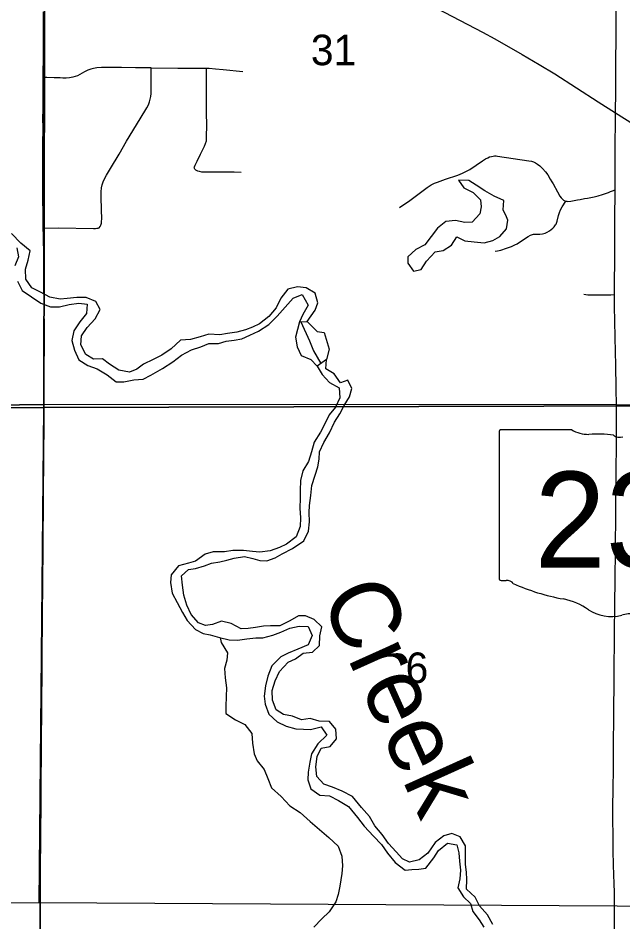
# Model space of a CAD drawing. Extents: x 0 to 34, y 0 to 22.
# Drawn here: x 3.685 to 4.1, y 14.389 to 15.009 of the extents above; entities that cross this region are included whole.
import ezdxf

# ---------------------------------------------------------------- set-up
doc = ezdxf.new("R2010")
doc.units = 0
for name, color, linetype in [('GM_X_Corporation', 7, 'Continuous'), ('GM_X_County_Road', 7, 'Continuous'), ('GM_X_Major_River', 7, 'Continuous'), ('GM_X_Major_River_Text', 7, 'Continuous'), ('GM_X_Minor_Lake', 7, 'Continuous'), ('GM_X_Minor_River', 7, 'Continuous'), ('GM_X_Section_Text', 7, 'Continuous'), ('GM_X_State_Location', 7, 'Continuous'), ('GM_X_State_Route', 7, 'Continuous'), ('GM_X_State_Shield', 7, 'Continuous'), ('GM_X_Township_Road', 7, 'Continuous'), ('GM_X_US_Route', 7, 'Continuous')]:
    doc.layers.add(name, color=color, linetype=linetype)

msp = doc.modelspace()

# ---------------------------------------------------------------- linework, layer by layer
at = {"layer": 'GM_X_Corporation'}
for points in [[(3.70377, 15.25213), (4.22309, 15.24934), (4.21755, 14.74349), (3.70275, 14.74227), (3.70371, 15.24512)], [(3.19551, 15.23797), (3.70371, 15.24512), (3.70275, 14.74227), (3.19987, 14.73736)], [(4.21755, 14.74349), (4.22002, 14.74366), (4.21532, 14.39943), (3.69961, 14.40239), (3.70275, 14.74227)], [(3.19987, 14.73736), (3.70275, 14.74227), (3.69961, 14.40239), (3.19505, 14.4011), (3.19438, 14.73721)]]:
    msp.add_lwpolyline(points, close=True, dxfattribs=at)
for points in [[(3.23219, 14.73782), (3.70287, 14.74434), (3.70292, 14.75501), (3.70303, 14.76775), (3.70304, 14.77242), (3.70314, 14.78236), (3.70311, 14.79541), (3.70302, 14.81125), (3.70283, 14.82865), (3.70272, 14.84636), (3.70258, 14.86004), (3.70248, 14.86546), (3.70234, 14.87231), (3.70232, 14.87417), (3.70228, 14.87728), (3.70217, 14.88318), (3.70216, 14.89312), (3.70214, 14.90181), (3.70217, 14.90647), (3.70219, 14.91392), (3.70222, 14.92325), (3.70226, 14.93319), (3.70225, 14.94159), (3.70238, 14.94561), (3.70236, 14.9484), (3.70239, 14.95057), (3.70236, 14.95615), (3.70235, 14.96081), (3.70234, 14.96547), (3.70235, 14.96878), (3.70235, 14.96921), (3.70251, 14.98412), (3.70254, 14.99252), (3.70258, 15.00309), (3.70261, 15.01364)], [(4.46985, 14.74372), (4.0958, 14.74406), (3.70287, 14.74434), (3.70292, 14.75501), (3.70303, 14.76775), (3.70304, 14.77242), (3.70314, 14.78236), (3.70311, 14.79541), (3.70302, 14.81125), (3.70283, 14.82865), (3.70272, 14.84636), (3.70258, 14.86004), (3.70248, 14.86546), (3.70234, 14.87231), (3.70232, 14.87417), (3.70228, 14.87728), (3.70217, 14.88318), (3.70216, 14.89312), (3.70214, 14.90181), (3.70217, 14.90647), (3.70219, 14.91392), (3.70222, 14.92325), (3.70226, 14.93319), (3.70225, 14.94159), (3.70238, 14.94561), (3.70236, 14.9484), (3.70239, 14.95057), (3.70236, 14.95615), (3.70235, 14.96081), (3.70234, 14.96547), (3.70235, 14.96878), (3.70235, 14.96921), (3.70251, 14.98412), (3.70254, 14.99252), (3.70258, 15.00309), (3.70261, 15.01364)], [(3.70019, 14.37188), (3.7003, 14.3899), (3.70042, 14.40576), (3.7004, 14.42254), (3.70061, 14.4502), (3.70081, 14.47103), (3.70082, 14.48439), (3.70098, 14.50614), (3.7011, 14.51919), (3.70113, 14.52883), (3.70121, 14.54095), (3.70143, 14.56051), (3.70145, 14.56113), (3.70146, 14.56205), (3.70145, 14.56236), (3.70145, 14.56298), (3.70144, 14.56328), (3.70145, 14.56421), (3.70148, 14.56856), (3.70155, 14.56979), (3.7015, 14.57383), (3.70148, 14.58004), (3.70164, 14.58936), (3.70167, 14.59495), (3.7019, 14.62604), (3.70208, 14.6422), (3.70213, 14.65277), (3.70234, 14.67546), (3.70237, 14.68478), (3.7025, 14.70498), (3.70283, 14.73543), (3.70287, 14.74434), (3.23219, 14.73782)], [(4.46985, 14.74372), (4.0958, 14.74406), (3.70287, 14.74434), (3.70283, 14.73543), (3.7025, 14.70498), (3.70237, 14.68478), (3.70234, 14.67546), (3.70213, 14.65277), (3.70208, 14.6422), (3.7019, 14.62604), (3.70167, 14.59495), (3.70164, 14.58936), (3.70148, 14.58004), (3.7015, 14.57383), (3.70155, 14.56979), (3.70148, 14.56856), (3.70145, 14.56421), (3.70144, 14.56328), (3.70145, 14.56298), (3.70145, 14.56236), (3.70146, 14.56205), (3.70145, 14.56113), (3.70143, 14.56051), (3.70121, 14.54095), (3.70113, 14.52883), (3.7011, 14.51919), (3.70098, 14.50614), (3.70082, 14.48439), (3.70081, 14.47103), (3.70061, 14.4502), (3.7004, 14.42254), (3.70042, 14.40576), (3.7003, 14.3899), (3.70019, 14.37188)]]:
    msp.add_lwpolyline(points, dxfattribs=at)
at = {"layer": 'GM_X_County_Road'}
for points in [[(3.70259, 14.86518), (3.70245, 14.87203), (3.70244, 14.8739), (3.70239, 14.877), (3.70229, 14.88291), (3.70227, 14.89284), (3.70226, 14.90153), (3.70229, 14.90619), (3.7023, 14.91364), (3.70233, 14.92297), (3.70237, 14.93292), (3.70236, 14.94131), (3.70249, 14.94533), (3.70248, 14.94812), (3.7025, 14.95029), (3.70247, 14.95588), (3.70246, 14.96053), (3.70245, 14.9652), (3.70246, 14.96851), (3.70246, 14.96893), (3.70262, 14.98385), (3.70265, 14.99224), (3.70269, 15.00281), (3.70272, 15.01337)], [(3.70298, 14.74357), (3.70298, 14.74406), (3.70304, 14.75474), (3.70314, 14.76748), (3.70316, 14.77215), (3.70325, 14.78208), (3.70322, 14.79513), (3.70313, 14.81097), (3.70294, 14.82837), (3.70283, 14.84609), (3.70269, 14.85977), (3.70259, 14.86518)], [(3.7003, 14.3716), (3.70041, 14.38963), (3.70053, 14.40548), (3.70052, 14.42227), (3.70072, 14.44993), (3.70092, 14.47075), (3.70093, 14.48412), (3.7011, 14.50587), (3.70121, 14.51892), (3.70124, 14.52856), (3.70133, 14.54068), (3.70154, 14.56024), (3.70156, 14.56085), (3.70157, 14.56177), (3.70156, 14.56208), (3.70156, 14.5627), (3.70156, 14.56393), (3.70159, 14.56828), (3.70166, 14.56952), (3.70162, 14.57356), (3.70159, 14.57977), (3.70175, 14.58908), (3.70178, 14.59468), (3.70201, 14.62576), (3.70219, 14.64192), (3.70225, 14.65249), (3.70245, 14.67518), (3.70248, 14.6845), (3.70262, 14.7047), (3.70294, 14.73516), (3.70298, 14.74357)]]:
    msp.add_lwpolyline(points, dxfattribs=at)
at = {"layer": 'GM_X_Major_River'}
for points in [[(3.74309, 14.77558), (3.73702, 14.77525), (3.73173, 14.77851), (3.72817, 14.78518), (3.72859, 14.79125), (3.73262, 14.7971), (3.73798, 14.80294), (3.74144, 14.80936), (3.73844, 14.81489), (3.73182, 14.81759), (3.72537, 14.81764), (3.71892, 14.81693), (3.71398, 14.8164), (3.70697, 14.81778), (3.70054, 14.82125), (3.6945, 14.82433), (3.69036, 14.83024), (3.69022, 14.83707), (3.69198, 14.84332), (3.69335, 14.84957), (3.68694, 14.85493), (3.68073, 14.86143)], [(3.68426, 14.85173), (3.68535, 14.84546), (3.68303, 14.8394)], [(3.68485, 14.82876), (3.68803, 14.82248), (3.69445, 14.81807), (3.70087, 14.81384), (3.7073, 14.81133), (3.71356, 14.81128), (3.72021, 14.81294), (3.72686, 14.81384), (3.73255, 14.81304), (3.73212, 14.80659), (3.72753, 14.80093), (3.7235, 14.7947), (3.72212, 14.78807), (3.72378, 14.78161), (3.72696, 14.77494), (3.733, 14.7711), (3.73943, 14.76859), (3.74623, 14.76455), (3.75246, 14.75976), (3.75777, 14.75972), (3.76461, 14.76119), (3.77107, 14.76171), (3.77621, 14.76432), (3.78421, 14.76901), (3.79127, 14.77351)], [(3.88349, 14.80126), (3.88905, 14.809), (3.89079, 14.81392), (3.88913, 14.82057), (3.8829, 14.82423), (3.87683, 14.82484), (3.87018, 14.82337), (3.86558, 14.81715), (3.86231, 14.81053), (3.85714, 14.8045), (3.85084, 14.79961), (3.84608, 14.79737), (3.84114, 14.79552), (3.83524, 14.79385), (3.82897, 14.79295), (3.82366, 14.79204), (3.81607, 14.79248), (3.81017, 14.79063), (3.80352, 14.78878), (3.79669, 14.78845), (3.79019, 14.78243), (3.78371, 14.77812), (3.77781, 14.77513), (3.77133, 14.77195), (3.76656, 14.76838), (3.76161, 14.76633), (3.75441, 14.76772), (3.748, 14.77194), (3.74309, 14.77558)], [(3.79127, 14.77351), (3.79737, 14.77801), (3.80423, 14.78176), (3.81069, 14.78379), (3.81602, 14.78603), (3.82266, 14.78598), (3.82799, 14.78765), (3.83349, 14.78836), (3.83881, 14.78927), (3.84415, 14.79189), (3.85024, 14.7945), (3.85729, 14.799), (3.86302, 14.80483), (3.86838, 14.81106), (3.87393, 14.81708), (3.88021, 14.81969), (3.88414, 14.81245), (3.88068, 14.80603), (3.87836, 14.80092), (3.88349, 14.80126)], [(3.88349, 14.80126), (3.89046, 14.79438), (3.8952, 14.79359), (3.89869, 14.78228), (3.89677, 14.77517)], [(3.89677, 14.77517), (3.89047, 14.77048), (3.89385, 14.76476), (3.89893, 14.75941), (3.90554, 14.75556), (3.90587, 14.74892), (3.90298, 14.7423), (3.89858, 14.73721), (3.89569, 14.73098), (3.89261, 14.72531), (3.88838, 14.71832), (3.88663, 14.71169), (3.88449, 14.70507), (3.88065, 14.69865), (3.87908, 14.69202), (3.87865, 14.68519), (3.8788, 14.67988), (3.87856, 14.67305), (3.8789, 14.6666), (3.87866, 14.66053), (3.87595, 14.65353), (3.86928, 14.64846), (3.86452, 14.64622), (3.85824, 14.6438), (3.85102, 14.64291), (3.84609, 14.64333), (3.83984, 14.64413), (3.83243, 14.644), (3.82674, 14.64328), (3.81915, 14.64315), (3.81344, 14.64149), (3.80696, 14.63679), (3.80221, 14.6355), (3.79536, 14.63366), (3.79019, 14.62743), (3.78977, 14.62213), (3.79086, 14.61491), (3.79442, 14.60843), (3.79797, 14.60157), (3.80116, 14.59605), (3.80699, 14.58993), (3.8121, 14.58724), (3.81702, 14.58625), (3.82346, 14.5845), (3.83009, 14.58293), (3.83578, 14.5827), (3.84205, 14.5836), (3.84831, 14.58412), (3.85306, 14.58427), (3.86009, 14.58612), (3.86542, 14.58816), (3.8717, 14.59077), (3.87797, 14.59224), (3.88423, 14.592), (3.88703, 14.58572), (3.88414, 14.57948), (3.87709, 14.5765), (3.87062, 14.57371), (3.86548, 14.57109), (3.85937, 14.56506), (3.85666, 14.55788), (3.8549, 14.55125), (3.85409, 14.54424), (3.85481, 14.53873), (3.85722, 14.53188), (3.86288, 14.52653), (3.86912, 14.52363), (3.87574, 14.52169), (3.88105, 14.52146), (3.8858, 14.52142), (3.89321, 14.52307), (3.89715, 14.51754), (3.89085, 14.51152), (3.88643, 14.50453), (3.88544, 14.49885), (3.88425, 14.49203), (3.88402, 14.48672), (3.88606, 14.48063), (3.89229, 14.47622), (3.89893, 14.47579), (3.90517, 14.47252), (3.91197, 14.46849), (3.91817, 14.46085), (3.92268, 14.45494), (3.92908, 14.44806), (3.93454, 14.44233), (3.93867, 14.4366), (3.94394, 14.43011), (3.95073, 14.42475), (3.95548, 14.42528), (3.96022, 14.42544), (3.96497, 14.42616), (3.97052, 14.43333), (3.97379, 14.43823), (3.97989, 14.44331), (3.98634, 14.44231), (3.98763, 14.4368), (3.98815, 14.43111), (3.98887, 14.42484), (3.98825, 14.41878), (3.98707, 14.41271)], [(3.99221, 14.44151), (3.98846, 14.44761), (3.98279, 14.44993), (3.97747, 14.44845), (3.97136, 14.44375), (3.96637, 14.43658), (3.96046, 14.43189), (3.95381, 14.43023), (3.94889, 14.43254), (3.94475, 14.43732), (3.93929, 14.44305), (3.93497, 14.44934), (3.92989, 14.45526), (3.92634, 14.46155), (3.92088, 14.46785), (3.91467, 14.47529), (3.90768, 14.47895), (3.90087, 14.48185), (3.895, 14.48379), (3.89011, 14.48914), (3.8894, 14.49578), (3.8904, 14.5028), (3.8931, 14.50847), (3.89937, 14.50975), (3.90377, 14.51484), (3.90325, 14.52148), (3.89893, 14.52682), (3.89172, 14.52707), (3.88566, 14.52882), (3.87958, 14.52792), (3.87353, 14.53043), (3.86728, 14.53162), (3.86218, 14.53488), (3.85976, 14.54154), (3.85943, 14.54799), (3.86157, 14.55461), (3.86446, 14.56104), (3.87058, 14.56745), (3.87553, 14.56968), (3.88087, 14.57363), (3.88732, 14.57434), (3.8921, 14.57885), (3.89234, 14.58549), (3.89352, 14.59174), (3.88844, 14.59672), (3.88238, 14.59923), (3.87764, 14.59926), (3.87155, 14.59589), (3.86469, 14.59253), (3.85843, 14.59239), (3.85368, 14.59224), (3.84817, 14.59133), (3.84305, 14.59061), (3.8383, 14.59046), (3.8315, 14.59411), (3.82487, 14.59568), (3.81859, 14.59345), (3.81384, 14.59273), (3.80892, 14.59447), (3.80384, 14.6002), (3.80086, 14.60668), (3.79901, 14.61352), (3.79792, 14.62036), (3.79721, 14.62681), (3.80217, 14.63095), (3.80692, 14.63186), (3.81301, 14.63352), (3.81795, 14.63538), (3.82365, 14.63629), (3.8284, 14.63739), (3.83335, 14.63887), (3.84056, 14.63995), (3.84625, 14.63858), (3.85117, 14.63722), (3.85591, 14.63699), (3.86162, 14.63903), (3.86638, 14.64184), (3.87343, 14.64539), (3.88125, 14.65084), (3.88452, 14.65745), (3.88514, 14.66371), (3.88499, 14.67016), (3.88522, 14.6749), (3.88603, 14.68191), (3.88684, 14.68874), (3.88898, 14.69574), (3.89091, 14.70142), (3.89171, 14.70672), (3.89213, 14.71184), (3.89502, 14.71827), (3.89887, 14.72488), (3.90233, 14.73206), (3.90598, 14.73792), (3.90887, 14.74359), (3.91252, 14.74944), (3.91427, 14.75531), (3.91146, 14.76102), (3.90633, 14.75916), (3.90201, 14.76527), (3.89634, 14.76872), (3.89677, 14.77517)], [(4.01098, 14.38768), (4.00723, 14.39416), (4.00178, 14.40027), (3.99878, 14.40637), (3.99294, 14.41172), (3.99318, 14.41855), (3.99284, 14.42348), (3.99212, 14.4288), (3.99221, 14.44151)], [(3.98707, 14.41271), (3.99082, 14.40662), (3.99572, 14.40203), (3.99719, 14.39651), (4.00171, 14.39079), (4.00489, 14.38564)]]:
    msp.add_lwpolyline(points, dxfattribs=at)
at = {"layer": 'GM_X_Minor_Lake'}
for points in [[(4.0203, 14.87295), (4.01819, 14.87765), (4.01843, 14.88409), (4.01181, 14.88718), (4.00557, 14.89083), (3.99953, 14.89467), (3.99443, 14.89794), (3.98741, 14.89818), (3.99117, 14.89284), (3.99741, 14.88957), (4.00249, 14.88459), (4.00303, 14.87985), (4.00204, 14.87492), (3.99688, 14.86927), (3.99175, 14.86912), (3.98531, 14.8705), (3.97867, 14.86979), (3.97294, 14.86509), (3.96432, 14.85377), (3.95823, 14.85059), (3.95269, 14.84551)], [(3.95269, 14.84551), (3.95265, 14.84115), (3.9566, 14.83562), (3.96173, 14.83672), (3.96557, 14.84257), (3.9713, 14.84898), (3.977, 14.84988), (3.98272, 14.85344), (3.98618, 14.8593), (3.99185, 14.85641), (3.99811, 14.85579), (4.00493, 14.85517), (4.01102, 14.85683), (4.01578, 14.85945), (4.02037, 14.86473), (4.02136, 14.8706), (4.0203, 14.87295)], [(3.88349, 14.80126), (3.89046, 14.79438), (3.8952, 14.79359), (3.89869, 14.78228), (3.89677, 14.77517)]]:
    msp.add_lwpolyline(points, dxfattribs=at)
at = {"layer": 'GM_X_Minor_River'}
for points in [[(3.87836, 14.80092), (3.87563, 14.79051), (3.87672, 14.78386), (3.87952, 14.77796), (3.88614, 14.77506), (3.89047, 14.77048)], [(3.87926, 14.80098), (3.8851, 14.78797), (3.88789, 14.78112), (3.89294, 14.77232)], [(3.82379, 14.58442), (3.82457, 14.58107), (3.82888, 14.57383), (3.82847, 14.5689), (3.82672, 14.56323), (3.82724, 14.55677), (3.82814, 14.54993), (3.82791, 14.54406), (3.82766, 14.53704), (3.82782, 14.53229), (3.83443, 14.52788), (3.84085, 14.5248), (3.84555, 14.5185), (3.84607, 14.51186), (3.84716, 14.50464), (3.84921, 14.49988), (3.8541, 14.49397), (3.85652, 14.48769), (3.85913, 14.48122), (3.86572, 14.47529), (3.87175, 14.46898), (3.87873, 14.46437), (3.88571, 14.45825), (3.89193, 14.4527), (3.89853, 14.44734), (3.90494, 14.44141), (3.90735, 14.43438), (3.90787, 14.42773), (3.90745, 14.42261), (3.90606, 14.4139), (3.90488, 14.40822), (3.90314, 14.40311), (3.89872, 14.39631), (3.89356, 14.39142), (3.88821, 14.38577)]]:
    msp.add_lwpolyline(points, dxfattribs=at)
at = {"layer": 'GM_X_State_Route'}
for points in [[(4.09518, 14.94432), (4.09544, 14.95925), (4.09548, 14.96924), (4.09563, 15.00604), (4.09559, 15.02742), (4.09561, 15.03041)], [(4.09591, 14.74378), (4.09573, 14.7552), (4.09537, 14.77134), (4.09508, 14.78004), (4.09449, 14.81175), (4.09449, 14.81963), (4.09449, 14.82543), (4.09466, 14.84532), (4.09478, 14.87267), (4.09484, 14.88946), (4.09485, 14.8915), (4.09489, 14.8994), (4.09494, 14.9165), (4.09518, 14.94432)], [(4.09455, 14.37967), (4.09454, 14.3896), (4.09454, 14.40013), (4.09444, 14.40912), (4.0943, 14.41625), (4.09411, 14.42121), (4.09388, 14.42897), (4.09368, 14.43765), (4.09349, 14.44539), (4.09336, 14.46282), (4.09341, 14.4687), (4.09361, 14.47988), (4.09376, 14.4951), (4.09378, 14.50691), (4.09397, 14.53395), (4.09424, 14.55415), (4.09435, 14.56627), (4.09444, 14.57963), (4.0945, 14.58926), (4.09461, 14.60512), (4.09491, 14.62594), (4.0951, 14.64241), (4.09536, 14.67224), (4.09558, 14.69711), (4.09579, 14.71824), (4.09598, 14.73315), (4.09591, 14.74378)]]:
    msp.add_lwpolyline(points, dxfattribs=at)
at = {"layer": 'GM_X_State_Shield'}
for p, q in [((4.01524, 14.72523), (4.01524, 14.62517)), ((4.06512, 14.72695), (4.01686, 14.72695))]:
    msp.add_line(p, q, dxfattribs=at)
for centre, major_axis, start_param, end_param in [((4.01713, 14.72544), (0.00191, 0), 1.712693, 3.28349), ((4.07662, 14.73857), (0.01852, 0), 4.042523, 4.731795), ((4.08276, 14.67078), (0.06648, 0), 1.404758, 1.657858), ((4.09785, 14.72596), (0.00534, 0), 3.836095, 5.185415), ((4.01715, 14.62495), (0.00193, 0), 3.00124, 4.508301), ((4.01744, 14.63519), (0.0147, 0), 4.665946, 4.897461), ((4.02045, 14.6194), (0.0053, 0), 0.519207, 1.627899), ((4.08736, 14.7093), (0.1262, 0), 4.195997, 4.488961), ((4.04973, 14.58022), (0.03949, 0), 0.823519, 1.323587), ((4.09244, 14.6189), (0.02506, 0), 4.026481, 4.996735), ((4.10692, 14.58431), (0.02059, 0), 1.495662, 1.94098)]:
    msp.add_ellipse(centre, major_axis=major_axis, ratio=0.8, start_param=start_param, end_param=end_param, dxfattribs=at)
at = {"layer": 'GM_X_Township_Road'}
for points in [[(3.77657, 14.97512), (3.77255, 14.97517), (3.76572, 14.97516), (3.75608, 14.97527), (3.74239, 14.97532), (3.73929, 14.97513), (3.73683, 14.97475), (3.73503, 14.97428), (3.73299, 14.97352), (3.73075, 14.97244), (3.72751, 14.97059), (3.72587, 14.96971), (3.72443, 14.96914), (3.72264, 14.96869), (3.72051, 14.96837), (3.71806, 14.96817), (3.71589, 14.96813), (3.71403, 14.96819), (3.71153, 14.96829), (3.70998, 14.96836), (3.70485, 14.96846), (3.70246, 14.96851)], [(3.70259, 14.86518), (3.71289, 14.86546), (3.73681, 14.86506), (3.73828, 14.86499), (3.73931, 14.86509), (3.7402, 14.86526), (3.7407, 14.86552), (3.74147, 14.86639), (3.7419, 14.86723), (3.7423, 14.86852), (3.74249, 14.87002), (3.74261, 14.87147), (3.74245, 14.87798), (3.74222, 14.88636), (3.74225, 14.89008), (3.74249, 14.89287), (3.74291, 14.89499), (3.74359, 14.89706), (3.74451, 14.89903), (3.74584, 14.90149), (3.74853, 14.90603), (3.75445, 14.91589), (3.75962, 14.92475), (3.76893, 14.94018), (3.77342, 14.94763), (3.77458, 14.94983), (3.7754, 14.95184), (3.7759, 14.95364), (3.77622, 14.95547), (3.77638, 14.95764), (3.7765, 14.96541), (3.77657, 14.97512)], [(3.77657, 14.97512), (3.79469, 14.97498), (3.80919, 14.97495), (3.81456, 14.97487)], [(3.80651, 14.90574), (3.80629, 14.90605), (3.80613, 14.90633), (3.80601, 14.90679), (3.80613, 14.90733), (3.80661, 14.90831), (3.80802, 14.91105), (3.8104, 14.91604), (3.81304, 14.92134), (3.81389, 14.92334), (3.81437, 14.92514), (3.81458, 14.92731), (3.81463, 14.93634), (3.81457, 14.94381), (3.81448, 14.96062), (3.81454, 14.97182), (3.81456, 14.97487)], [(3.81456, 14.97487), (3.81637, 14.97484), (3.82073, 14.97458), (3.82602, 14.974), (3.83948, 14.97265)], [(3.94698, 14.87939), (3.95413, 14.88422), (3.96581, 14.89298), (3.9687, 14.8948), (3.97091, 14.89594), (3.9729, 14.89678), (3.97847, 14.8987), (3.98701, 14.90157), (3.99018, 14.90286), (3.99511, 14.90549), (4.00389, 14.91133), (4.00595, 14.91266), (4.00756, 14.91353), (4.00871, 14.914), (4.01001, 14.91437), (4.01114, 14.91464), (4.0121, 14.91474), (4.0127, 14.91476), (4.01328, 14.91472), (4.01424, 14.91458), (4.0356, 14.9114), (4.03758, 14.91103), (4.03832, 14.91086), (4.039, 14.91066), (4.04033, 14.91), (4.04173, 14.90916), (4.04317, 14.90805), (4.04516, 14.90607), (4.04719, 14.90372), (4.04864, 14.9017), (4.05045, 14.89881), (4.05154, 14.89694), (4.05229, 14.89558), (4.0553, 14.89017), (4.05702, 14.88722), (4.05791, 14.88594), (4.05876, 14.88503), (4.0595, 14.88448), (4.06032, 14.884), (4.06117, 14.88367)], [(3.80651, 14.90574), (3.80698, 14.90528), (3.80744, 14.90493), (3.80818, 14.90454), (3.80938, 14.9042), (3.81109, 14.90392), (3.8135, 14.90371), (3.81753, 14.90371), (3.82437, 14.90375), (3.83337, 14.90378), (3.83833, 14.90365)], [(4.06117, 14.88367), (4.0618, 14.88359), (4.06257, 14.88356), (4.06445, 14.88372), (4.06688, 14.88416), (4.069, 14.88459), (4.07083, 14.8849), (4.07389, 14.88544), (4.07602, 14.88585), (4.0806, 14.8867), (4.08331, 14.88735), (4.08631, 14.88822), (4.09034, 14.88966), (4.09174, 14.89022), (4.09303, 14.89075), (4.09485, 14.8915)], [(4.01259, 14.84931), (4.01413, 14.84958), (4.01652, 14.85016), (4.02048, 14.85149), (4.02377, 14.85268), (4.02614, 14.85367), (4.02772, 14.85447), (4.03008, 14.85596), (4.03531, 14.8595), (4.03681, 14.86034), (4.03752, 14.86069), (4.03822, 14.86091), (4.03894, 14.86106), (4.03967, 14.86108), (4.0403, 14.86102), (4.04178, 14.86103), (4.04333, 14.86103), (4.04511, 14.86132), (4.04694, 14.86178), (4.0483, 14.86238), (4.04982, 14.86328), (4.05114, 14.86423), (4.05224, 14.86521), (4.05305, 14.86612), (4.0541, 14.86741), (4.05449, 14.86801), (4.05473, 14.86863), (4.05516, 14.86998), (4.05609, 14.8739), (4.05676, 14.87596), (4.05746, 14.87774), (4.05855, 14.87975), (4.06117, 14.88367)], [(4.07352, 14.81984), (4.0763, 14.81947), (4.07884, 14.81935), (4.08745, 14.81936), (4.09189, 14.81953), (4.09449, 14.81963)]]:
    msp.add_lwpolyline(points, dxfattribs=at)
at = {"layer": 'GM_X_US_Route'}
for points in [[(3.70235, 15.15492), (3.72399, 15.14379), (3.74221, 15.13437), (3.75858, 15.12608), (3.77627, 15.11699), (3.78681, 15.11164), (3.83015, 15.08922), (3.86693, 15.07034), (3.88242, 15.06239), (3.93744, 15.03412), (3.97282, 15.01592), (4.00394, 14.99961), (4.0124, 14.99497), (4.03106, 14.98438), (4.04285, 14.97744), (4.05346, 14.97094), (4.08337, 14.95192), (4.09518, 14.94432)], [(4.09518, 14.94432), (4.11802, 14.92979), (4.13556, 14.91856), (4.15837, 14.90404), (4.17905, 14.89078), (4.21808, 14.86585), (4.25001, 14.8454), (4.2786, 14.82719), (4.31573, 14.80334), (4.32788, 14.79582), (4.34016, 14.7885), (4.34961, 14.78313), (4.357, 14.77918)]]:
    msp.add_lwpolyline(points, dxfattribs=at)

# ---------------------------------------------------------------- texts
at = {"layer": 'GM_X_Major_River_Text'}
msp.add_text('Creek', height=0.047365, rotation=294.22246, dxfattribs=at).set_placement((3.89226, 14.61221))
at = {"layer": 'GM_X_Section_Text'}
for s, height, p in [('31', 0.020928, (3.88611, 14.97696)), ('6', 0.02093, (3.95111, 14.55322))]:
    msp.add_text(s, height=height, rotation=0.00001, dxfattribs=at).set_placement(p)
at = {"layer": 'GM_X_State_Location'}
for s, p in [('s', (4.09579, 14.66855)), ('r', (4.09578, 14.66855))]:
    msp.add_text(s, height=0.0000947, dxfattribs=at).set_placement(p)
msp.add_text('231', height=0.0000947, rotation=0.00001, dxfattribs=at).set_placement((4.06236, 14.66166))
at = {"layer": 'GM_X_State_Shield'}
msp.add_text('231', height=0.065918, dxfattribs=at).set_placement((4.03952, 14.63223))

doc.saveas('drawing.dxf')
